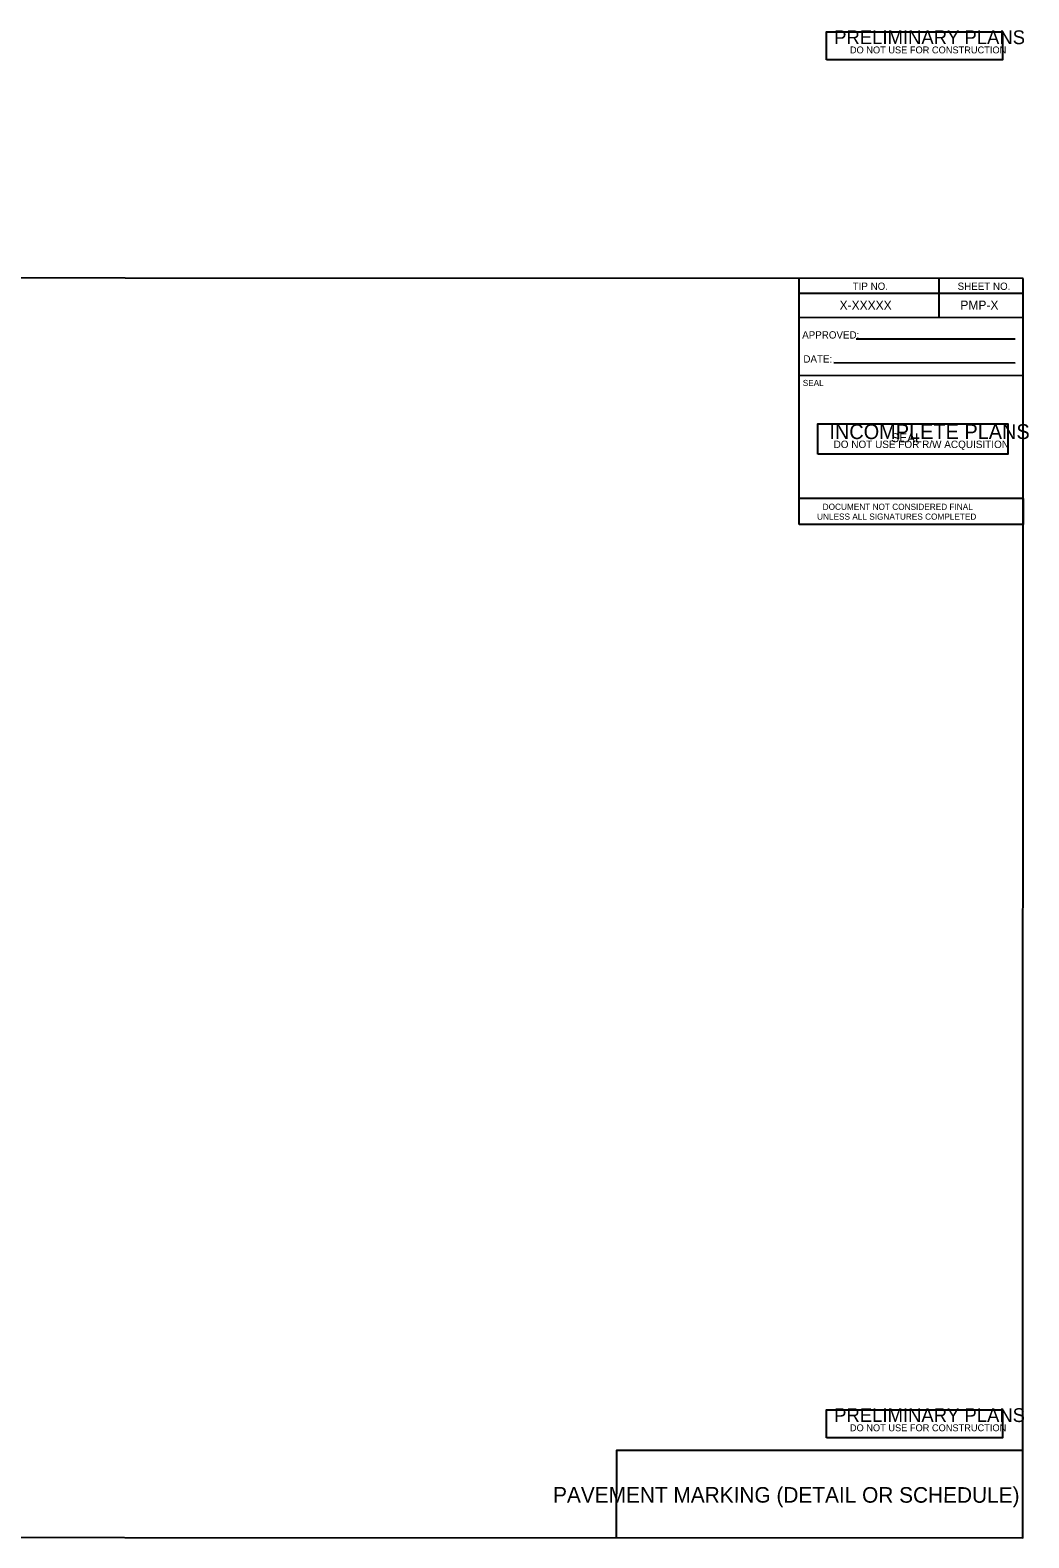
# Model space of a CAD drawing. Extents: x 2412958 to 2415566, y 564352 to 569392.
# Drawn here: x 2413932 to 2414765, y 566582 to 567840 of the extents above; entities that cross this region are included whole.
import ezdxf

# ---------------------------------------------------------------- set-up
doc = ezdxf.new("R2010")
doc.units = 0
for name, color, linetype in [('Default', 7, 'Continuous'), ('DEV BORDER CELL', 7, 'Continuous'), ('Old_Level_10', 7, 'Continuous'), ('Old_Level_4', 7, 'Continuous'), ('Sheet Sticker Exception Certification CELL', 7, 'Continuous'), ('Sheet Sticker Incomplete CELL', 7, 'Continuous'), ('Sheet Sticker Preliminary CELL', 7, 'Continuous'), ('Sheet Title CELL', 7, 'Continuous'), ('Typical Detail Wedge1 CELL', 7, 'Continuous')]:
    doc.layers.add(name, color=color, linetype=linetype)

msp = doc.modelspace()

# ---------------------------------------------------------------- linework, layer by layer
at = {"layer": 'DEV BORDER CELL'}
msp.add_lwpolyline([(2414760.3, 567632.6), (2413261, 567633.3), (2413260.5, 566582.2), (2414759.8, 566581.5)], close=True, dxfattribs=at)
at = {"layer": 'Old_Level_10'}
for p, q in [((2414690, 567600.1), (2414690, 567632.6)), ((2414690, 567607.7), (2414690, 567632.6)), ((2414760.3, 567632.6), (2414760.3, 567632.6)), ((2414760.3, 567632.6), (2414760.3, 567632.6)), ((2414760.3, 567632.6), (2414760.3, 567632.6)), ((2414760.3, 567632.6), (2414760.3, 567632.6)), ((2414760.3, 567632.6), (2414760.3, 567632.6)), ((2414760.3, 567632.6), (2414760.3, 567632.6)), ((2414760.3, 567632.6), (2414760.3, 567632.6)), ((2414760.3, 567632.6), (2414760.3, 567632.6)), ((2414573.3, 567620.5), (2414690, 567620.4)), ((2414690, 567620.4), (2414760.3, 567620.4)), ((2414573.3, 567600.2), (2414760.3, 567600.1)), ((2414620.9, 567582.3), (2414753.6, 567582.2)), ((2414602.3, 567562.4), (2414753.6, 567562.3))]:
    msp.add_line(p, q, dxfattribs=at)
at = {"layer": 'Sheet Sticker Exception Certification CELL'}
for p, q in [((2414573.2, 567427.2), (2414573.2, 567449.2)), ((2414573.2, 567449.2), (2414760.2, 567449.2)), ((2414760.2, 567449.1), (2414760.2, 567427.2)), ((2414760.2, 567427.2), (2414573.2, 567427.2))]:
    msp.add_line(p, q, dxfattribs=at)
at = {"layer": 'Sheet Sticker Incomplete CELL'}
msp.add_lwpolyline([(2414588.9, 567486), (2414588.9, 567511.3), (2414747.5, 567511.3), (2414747.5, 567486)], close=True, dxfattribs=at)
at = {"layer": 'Sheet Sticker Preliminary CELL'}
for points in [[(2414596, 567815), (2414596, 567838.5), (2414743, 567838.5), (2414743, 567815)], [(2414596, 566665), (2414596, 566688.5), (2414743, 566688.5), (2414743, 566665)]]:
    msp.add_lwpolyline(points, close=True, dxfattribs=at)
at = {"layer": 'Sheet Title CELL'}
for p, q in [((2414573.3, 567607.7), (2414573.3, 567632.7)), ((2414573.2, 567560.6), (2414573.3, 567607.7)), ((2414573.2, 567449.2), (2414573.2, 567560.6)), ((2414573.2, 567551.8), (2414760.2, 567551.7)), ((2414760.2, 567449.1), (2414573.2, 567449.2))]:
    msp.add_line(p, q, dxfattribs=at)
msp.add_lwpolyline([(2414420.6, 566581.7), (2414759.8, 566581.5), (2414759.8, 566654.4), (2414420.7, 566654.5)], close=True, dxfattribs=at)

# ---------------------------------------------------------------- texts
at = {"layer": 'Default'}
msp.add_text('PAVEMENT MARKING (DETAIL OR SCHEDULE)', height=13, rotation=359.9734, dxfattribs=at).set_placement((2414367.9, 566611))
at = {"layer": 'Old_Level_10'}
for s, height, p in [('TIP NO.', 6.11, (2414617.9, 567623.1)), ('SHEET NO.', 6.11, (2414705.5, 567623.1)), ('SEAL', 5.09, (2414576.3, 567542.9))]:
    msp.add_text(s, height=height, rotation=359.9683, dxfattribs=at).set_placement(p)
at = {"layer": 'Old_Level_4'}
for s, p in [('APPROVED:', (2414575.8, 567582.5)), ('DATE:', (2414576.8, 567562.4))]:
    msp.add_text(s, height=6.11, rotation=359.9683, dxfattribs=at).set_placement(p)
at = {"layer": 'Sheet Sticker Exception Certification CELL'}
for s, p in [('DOCUMENT NOT CONSIDERED FINAL', (2414592.9, 567439.5)), ('UNLESS ALL SIGNATURES COMPLETED', (2414588.2, 567431.3))]:
    msp.add_text(s, height=5.141, dxfattribs=at).set_placement(p)
at = {"layer": 'Sheet Sticker Incomplete CELL'}
for s, height, p in [('INCOMPLETE PLANS', 12.429, (2414598.5, 567498.6)), ('DO NOT USE FOR R/W ACQUISITION', 6.215, (2414602, 567491.1))]:
    msp.add_text(s, height=height, dxfattribs=at).set_placement(p)
at = {"layer": 'Sheet Sticker Preliminary CELL'}
for s, height, p in [('PRELIMINARY PLANS', 11.52, (2414602.5, 567828.2)), ('DO NOT USE FOR CONSTRUCTION', 5.76, (2414615.6, 567820.5)), ('PRELIMINARY PLANS', 11.52, (2414602.5, 566678.2)), ('DO NOT USE FOR CONSTRUCTION', 5.76, (2414615.6, 566670.5))]:
    msp.add_text(s, height=height, dxfattribs=at).set_placement(p)
at = {"layer": 'Sheet Title CELL'}
for s, p in [('X-XXXXX', (2414607, 567606.6)), ('PMP-X', (2414707.8, 567606.7))]:
    msp.add_text(s, height=7.5, rotation=359.9683, dxfattribs=at).set_placement(p)
at = {"layer": 'Typical Detail Wedge1 CELL'}
msp.add_text('SEAL', height=7.45, dxfattribs=at).set_placement((2414650.1, 567496))

doc.saveas('drawing.dxf')
